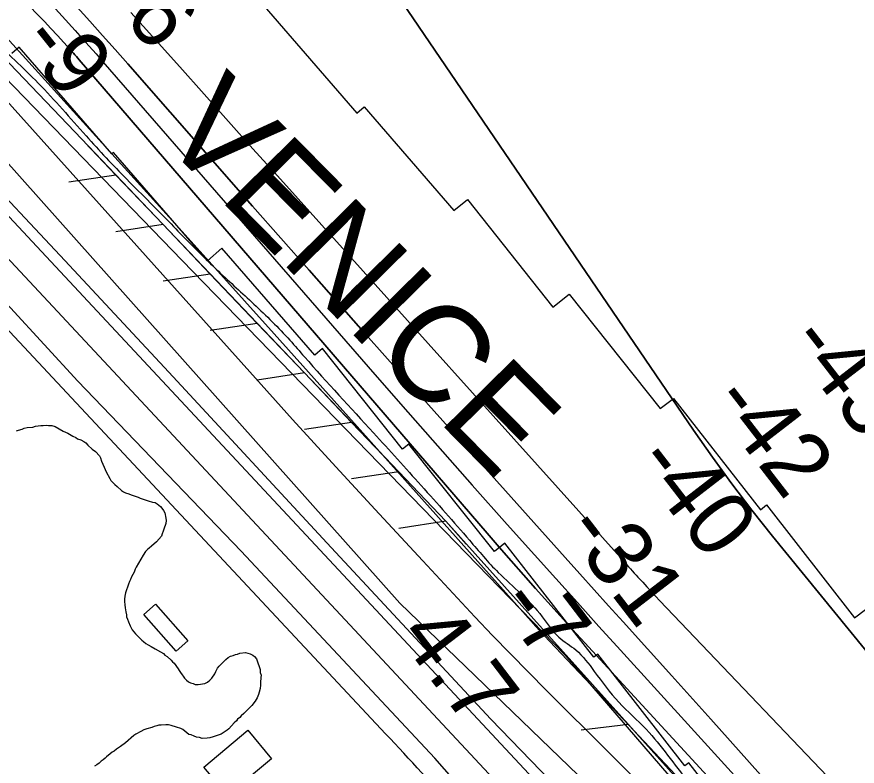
# Model space of a CAD drawing. Extents: x 3887375 to 3925618, y 296674 to 322633.
# Drawn here: x 3897472 to 3898333, y 306817 to 307585 of the extents above; entities that cross this region are included whole.
import ezdxf

# ---------------------------------------------------------------- set-up
doc = ezdxf.new("R2010")
doc.units = 0
for name, color, linetype in [('V-BLDG-OTLN', 7, 'Continuous'), ('V-LEVE-TOET', 7, 'Continuous'), ('V-RIVR-EDGE', 7, 'Continuous'), ('V-RIVR-RANG', 7, 'Continuous'), ('V-ROAD-CNTR', 7, 'Continuous'), ('V-RRAP-FSHR', 7, 'Continuous'), ('V-RRAP-RVMT', 7, 'Continuous'), ('V-RRAP-RVMT-IDEN', 7, 'Continuous'), ('V-SITE-VEGE', 7, 'Continuous'), ('V-SURV-LINE', 7, 'Continuous'), ('V-TOPO-DPTH', 7, 'Continuous'), ('V-TOPO-MINR', 7, 'Continuous'), ('V-TOPO-WATR', 7, 'Continuous')]:
    doc.layers.add(name, color=color, linetype=linetype)

msp = doc.modelspace()

# ---------------------------------------------------------------- linework, layer by layer
at = {"layer": 'V-BLDG-OTLN'}
for points in [[(3897614.19, 306982.77), (3897647.31, 306945.17), (3897635.62, 306934.86), (3897602.49, 306972.46)], [(3897663.96, 306816.07), (3897708.98, 306853.67), (3897733.3, 306824.55), (3897692.27, 306790.28), (3897684.88, 306799.12), (3897680.9, 306795.79)]]:
    msp.add_lwpolyline(points, close=True, dxfattribs=at)
at = {"layer": 'V-LEVE-TOET'}
for points in [[(3897628.06, 307220.48), (3897521.51, 307335.13), (3897424.58, 307438.31), (3897303.19, 307570.56), (3897169.65, 307712.92), (3897111.57, 307774.39), (3897068.91, 307820.25), (3896991.6, 307903.28), (3896953.77, 307940.82), (3896894.73, 307997.31), (3896828.08, 308063.5), (3896761.22, 308129.88), (3896689.75, 308201.41), (3896624.29, 308266.41), (3896558.04, 308331.41), (3896467.95, 308421.71), (3896374.06, 308516.16), (3896282.17, 308609.23), (3896193.87, 308699.73), (3896084.36, 308810.99), (3895985.85, 308912.76), (3895925.79, 308973.83)], [(3898424.48, 306234.02), (3898251.66, 306432.44), (3898086.45, 306611.84), (3898044.55, 306661.29), (3897900.68, 306825.16), (3897702.28, 307037.07), (3897534.9, 307211.24), (3897361.93, 307399.16)], [(3897628.06, 307220.48), (3897794.32, 307041.06), (3897958.05, 306864.95)], [(3897958.05, 306864.95), (3898152.73, 306664.02), (3898271.21, 306545.58), (3898354.85, 306454.31)]]:
    msp.add_lwpolyline(points, dxfattribs=at)
at = {"layer": 'V-RIVR-EDGE'}
msp.add_spline([(3894498.05, 310522.42), (3894530.03, 310496.11), (3894553.78, 310474.69), (3894579.94, 310451.31), (3894614.83, 310419.17), (3894633.24, 310400.67), (3894662.79, 310372.43), (3894685.08, 310353.44), (3894692.35, 310347.11), (3894709.79, 310328.13), (3894746.59, 310285.3), (3894785.84, 310252.18), (3894809.57, 310225.9), (3894830.41, 310205.45), (3894852.71, 310189.85), (3894866.75, 310171.85), (3894915.18, 310120.25), (3894950.06, 310083.74), (3894971.37, 310062.81), (3894999, 310039.43), (3895025.16, 310017.03), (3895052.79, 309992.68), (3895092.99, 309952.27), (3895110.91, 309932.8), (3895141.44, 309903.1), (3895188.91, 309855.88), (3895222.82, 309821.31), (3895255.75, 309784.32), (3895319.22, 309722.49), (3895350.7, 309688.42), (3895358.44, 309676.26), (3895364.73, 309669.44), (3895374.92, 309663.11), (3895388.97, 309650.44), (3895410.77, 309628.05), (3895448.54, 309583.28), (3895480.52, 309554.06), (3895503.76, 309527.78), (3895533.8, 309499.54), (3895577.4, 309454.75), (3895606.95, 309425.54), (3895653.45, 309378.81), (3895685.92, 309349.1), (3895719.83, 309314.54), (3895749.38, 309285.81), (3895790.55, 309242.49), (3895837.06, 309195.75), (3895863.69, 309164.12), (3895900.02, 309127.61), (3895944.1, 309081.37), (3895955.73, 309070.65), (3895974.63, 309054.58), (3896002.25, 309033.14), (3896032.78, 309003.93), (3896062.81, 308972.29), (3896082.67, 308950.39), (3896119.48, 308911.93), (3896139.34, 308892.46), (3896151.96, 308889.51), (3896163.12, 308883.66), (3896167.95, 308873.93), (3896170.35, 308862.27), (3896184.39, 308844.27), (3896211.03, 308816.04), (3896224.12, 308810.18), (3896236.73, 308802.37), (3896249.8, 308786.8), (3896255.61, 308776.59), (3896270.64, 308766.35), (3896280.32, 308753.22), (3896295.82, 308737.15), (3896375.27, 308661.2), (3896425.17, 308610.08), (3896464.41, 308570.65), (3896519.63, 308515.64), (3896548.69, 308483.03), (3896563.22, 308467.45), (3896597.61, 308430.94), (3896635.89, 308396.37), (3896666.41, 308365.7), (3896681.42, 308349.64), (3896712.43, 308320.42), (3896746.34, 308287.31), (3896777.36, 308260.04), (3896801.58, 308235.7), (3896820.47, 308215.26), (3896842.76, 308195.29), (3896851.46, 308181.19), (3896882.46, 308148.57), (3896918.81, 308116.43), (3896962.9, 308074.56), (3896997.76, 308033.19), (3897029.24, 307998.63), (3897042.32, 307985), (3897083.5, 307945.57), (3897107.23, 307918.31), (3897123.21, 307898.85), (3897130, 307898.83), (3897142.13, 307892.97), (3897145.99, 307882.28), (3897149.85, 307874.01), (3897162.93, 307860.38), (3897188.6, 307833.12), (3897229.29, 307788.83), (3897267.56, 307752.31), (3897300.5, 307715.81), (3897334.4, 307680.27), (3897361.53, 307651.07), (3897384.78, 307628.19), (3897411.42, 307598.98), (3897445.81, 307563.45), (3897494.26, 307516.71), (3897543.17, 307462.68), (3897584.83, 307418.38), (3897609.05, 307394.04), (3897646.83, 307355.58), (3897678.81, 307323.94), (3897715.15, 307290.34), (3897751.96, 307253.34), (3897766.97, 307236.31), (3897837.68, 307158.43), (3897886.6, 307104.4), (3897936, 307048.43), (3897965.54, 307015.34), (3898010.59, 306970.06), (3898027.54, 306949.14), (3898044.99, 306935.98), (3898063.87, 306914.08), (3898089.05, 306882.46), (3898117.14, 306854.7), (3898160.23, 306801.18), (3898195.59, 306763.7), (3898235.79, 306719.89), (3898261.46, 306693.6), (3898297.3, 306650.78), (3898332.65, 306612.33), (3898369.94, 306568.04), (3898397.54, 306534.95), (3898422.23, 306505.75), (3898462.9, 306455.14), (3898495.34, 306417.18), (3898521.97, 306382.15), (3898601.37, 306284.34), (3898652.22, 306228.37), (3898693.37, 306177.28), (3898729.68, 306130.57), (3898777.13, 306074.12), (3898825.55, 306014.26), (3898848.79, 305986.04), (3898903.98, 305917.43), (3898957.25, 305854.65), (3898984.35, 305818.16), (3899049.73, 305744.67), (3899107.84, 305679.45), (3899129.14, 305651.72), (3899142.69, 305630.31), (3899156.24, 305611.83), (3899175.12, 305587.98), (3899224.03, 305529.59), (3899255.99, 305493.57), (3899288.9, 305449.3), (3899312.61, 305415.24), (3899375.55, 305336.9), (3899410.9, 305296.02), (3899442.85, 305252.24), (3899470.43, 305211.86), (3899531.42, 305133.52), (3899579.35, 305071.24), (3899616.14, 305025.99), (3899647.13, 304986.09), (3899690.7, 304931.1), (3899729.41, 304876.62), (3899753.62, 304846.93), (3899770.56, 304821.64), (3899817.5, 304755.48), (3899845.56, 304713.16), (3899868.3, 304677.16), (3899889.6, 304650.4), (3899911.39, 304623.64), (3899955.44, 304569.14), (3899987.39, 304526.81), (3900012.56, 304494.21), (3900025.63, 304476.21), (3900037.24, 304456.75), (3900061.94, 304431.93), (3900070.67, 304424.13), (3900074.53, 304414.41), (3900074.99, 304404.21), (3900073.03, 304397.9), (3900071.55, 304388.68), (3900071.54, 304383.82), (3900075.9, 304378.96), (3900087.05, 304374.07), (3900096.26, 304367.74), (3900108.39, 304362.37), (3900117.11, 304353.6), (3900140.84, 304326.35), (3900165.54, 304299.09), (3900226.07, 304227.55), (3900277.87, 304164.29), (3900319.98, 304105.91), (3900352.41, 304062.61), (3900384.36, 304023.2), (3900411.47, 303988.16), (3900438.1, 303954.1), (3900462.8, 303926.85), (3900556.24, 303812.49), (3900597.89, 303762.85), (3900633.71, 303716.63), (3900652.59, 303691.33), (3900701.96, 303626.62), (3900774.57, 303530.77), (3900849.12, 303437.34), (3900903.35, 303371.16), (3900928.05, 303343.42), (3900948.87, 303317.63), (3901001.17, 303258.26), (3901038.95, 303216.88), (3901074.78, 303173.09), (3901092.2, 303147.31), (3901171.6, 303050.47), (3901205, 303008.62), (3901238.41, 302968.23), (3901274.74, 302927.83), (3901303.3, 302893.77), (3901343.98, 302847.53), (3901366.73, 302816.4), (3901404.5, 302770.17), (3901454.38, 302715.17), (3901507.18, 302659.19), (3901551.73, 302608.09), (3901584.66, 302570.61), (3901650.02, 302491.29), (3901680.99, 302443.62), (3901717.76, 302388.17), (3901785.52, 302298.16), (3901789.55, 302293.3)], degree=3, dxfattribs=at)
at = {"layer": 'V-ROAD-CNTR'}
msp.add_lwpolyline([(3897850.15, 306850.22), (3897084.5, 307668.93)], dxfattribs=at)
msp.add_spline([(3898676.43, 305915.91), (3898551.87, 306070.29), (3898364.89, 306290.32), (3898192.19, 306484.1), (3897998.73, 306690.52), (3897850.15, 306850.22)], degree=3, dxfattribs=at)
at = {"layer": 'V-RRAP-FSHR'}
for p, q in [((3897573.77, 307422.51), (3897525.49, 307415.18)), ((3897622.06, 307371.84), (3897573.78, 307364.52)), ((3897670.36, 307321.17), (3897622.08, 307313.85)), ((3897718.66, 307270.5), (3897670.38, 307263.18)), ((3897766.95, 307219.84), (3897718.67, 307212.51)), ((3897815.25, 307169.17), (3897766.97, 307161.84)), ((3897863.55, 307118.5), (3897815.27, 307111.17)), ((3897911.84, 307067.83), (3897863.57, 307060.51)), ((3898098.95, 306859.53), (3898050.48, 306853.64))]:
    msp.add_line(p, q, dxfattribs=at)
for points in [[(3891468.38, 312810.08), (3891592.07, 312735.45), (3892299.93, 312230.23), (3893039.21, 311719.28), (3893631.65, 311277.12), (3894117.75, 310846), (3894636.93, 310371.58), (3895241.96, 309786.83), (3895348.82, 309658.26), (3895604.32, 309398.25), (3896430.18, 308555.06), (3897023.94, 307973.73), (3897641.56, 307335.08), (3898033.61, 306930.91), (3898562.18, 306317.87), (3899280.35, 305434.23), (3899629.7, 304981.52), (3900046.19, 304414.8), (3900422.65, 303959.37), (3901188.76, 303011.8), (3901775.81, 302279.78)], [(3900183.19, 304271.3), (3899817.13, 304740.59), (3899520.95, 305137.04), (3899332.27, 305381.1), (3899099.29, 305675.47), (3898876.14, 305945.24), (3898644, 306227.35), (3898359.55, 306569.44), (3897911.75, 307067.92), (3897531.56, 307466.79), (3897152.78, 307863.36), (3896930.63, 308096.06), (3896288.11, 308742.08), (3895667.71, 309363.71), (3895267.02, 309773.18), (3894693.57, 310343.47)], [(3897573.77, 307422.51), (3897541.9, 307455.94)], [(3897622.06, 307371.84), (3897573.77, 307422.51)], [(3897670.36, 307321.17), (3897622.06, 307371.84)], [(3897718.66, 307270.5), (3897670.36, 307321.17)], [(3897766.95, 307219.84), (3897718.66, 307270.51)], [(3897815.25, 307169.17), (3897766.95, 307219.84)], [(3897863.55, 307118.5), (3897815.25, 307169.17)], [(3897911.84, 307067.83), (3897911.75, 307067.92), (3897863.55, 307118.5)], [(3897932.79, 307044.51), (3897911.84, 307067.83)], [(3898098.95, 306859.53), (3898077.57, 306883.34)], [(3898145.73, 306807.46), (3898098.95, 306859.54)]]:
    msp.add_lwpolyline(points, dxfattribs=at)
at = {"layer": 'V-RRAP-RVMT'}
for p, q in [((3897725.62, 307595.67), (3897820.77, 307486)), ((3897474.5, 307553.64), (3897467.16, 307547.28)), ((3897569.54, 307444.17), (3897474.5, 307553.64)), ((3897820.77, 307486), (3897828.19, 307492.35)), ((3897828.19, 307492.35), (3897920.15, 307386.41)), ((3897571.34, 307445.73), (3897569.54, 307444.17)), ((3897667.77, 307334.74), (3897571.34, 307445.73)), ((3897920.15, 307386.41), (3897934.1, 307397.41)), ((3897934.1, 307397.41), (3898021.6, 307287.3)), ((3897682.39, 307347.52), (3897667.77, 307334.74)), ((3897777.5, 307238.08), (3897682.39, 307347.52)), ((3898021.6, 307287.3), (3898038.25, 307300.49)), ((3898038.25, 307300.49), (3898131.4, 307183.22)), ((3897785.49, 307245.02), (3897777.5, 307238.08)), ((3897867.56, 307141.69), (3897785.49, 307245.02)), ((3898131.4, 307183.22), (3898144.94, 307193.78)), ((3898144.94, 307193.78), (3898234.04, 307079.59)), ((3897874.07, 307146.88), (3897867.56, 307141.69)), ((3897961.58, 307036.81), (3897874.07, 307146.88)), ((3898234.04, 307079.59), (3898240.41, 307084.56)), ((3898240.41, 307084.56), (3898330.66, 306968.92)), ((3897972.31, 307045.36), (3897961.58, 307036.81)), ((3898063.43, 306928.57), (3897972.31, 307045.36)), ((3898330.66, 306968.92), (3898341.67, 306977.5)), ((3898067.4, 306931.66), (3898063.43, 306928.57)), ((3898156.73, 306817.18), (3898067.4, 306931.66)), ((3898160.84, 306820.38), (3898156.73, 306817.18)), ((3898251.12, 306704.69), (3898160.84, 306820.38))]:
    msp.add_line(p, q, dxfattribs=at)
at = {"layer": 'V-SITE-VEGE'}
for points in [[(3897472.04, 307160.44), (3897474.15, 307161.2), (3897477.57, 307162.2), (3897479.94, 307163.22), (3897482.83, 307163.96), (3897488.6, 307164.41), (3897491.48, 307165.15), (3897496.73, 307165.86), (3897499.09, 307166.09), (3897502.5, 307166.31), (3897504.85, 307166.01), (3897507.99, 307165.97), (3897511.38, 307164.88), (3897519.69, 307160.05), (3897522.03, 307158.97), (3897524.38, 307158.15), (3897529.58, 307155.2), (3897532.7, 307153.59), (3897534.51, 307152.26), (3897537.9, 307151.16), (3897540.76, 307149.55), (3897542.83, 307148.21), (3897545.16, 307145.83), (3897549.55, 307141.84)], [(3897549.55, 307141.84), (3897552.92, 307139.17), (3897557.05, 307134.93), (3897558.07, 307132.82), (3897559.07, 307129.4), (3897561.87, 307123.34)], [(3897561.87, 307123.34), (3897563.89, 307118.34), (3897567.47, 307111.74), (3897568.75, 307109.63), (3897570.55, 307107.51), (3897572.62, 307105.39), (3897574.95, 307103.52), (3897579.35, 307099.53), (3897581.68, 307097.93), (3897583.76, 307096.85), (3897586.89, 307096.03), (3897589.5, 307094.95), (3897593.67, 307093.58), (3897596.53, 307092.49), (3897598.61, 307091.42), (3897606.96, 307088.95), (3897611.38, 307087.31), (3897614.12, 307087.21), (3897615.93, 307085.61), (3897617.75, 307084.28), (3897619.3, 307082.95), (3897620.85, 307081.36), (3897622.65, 307078.98), (3897623.93, 307076.34), (3897624.9, 307071.09), (3897625.13, 307068.73), (3897624.82, 307065.59), (3897622.91, 307059.86), (3897622.36, 307057.77), (3897621.01, 307054.91), (3897620.46, 307052.56), (3897615.4, 307046.87), (3897610.11, 307042.49), (3897607.98, 307040.42), (3897606.39, 307039.14), (3897604.27, 307036.81), (3897601.86, 307033.18), (3897594.62, 307020.97), (3897593.55, 307018.89), (3897592.46, 307015.76), (3897589.77, 307010.83), (3897588.69, 307008.22), (3897587.61, 307006.14), (3897586.79, 307003.27), (3897583.52, 306994.41), (3897582.95, 306991.02), (3897582.65, 306988.14), (3897582.62, 306985.79), (3897582.83, 306982.12), (3897583.31, 306979.23), (3897583.78, 306975.03), (3897584.52, 306971.88), (3897584.76, 306969.78), (3897585.51, 306967.42), (3897586.52, 306964.79), (3897588.3, 306960.83), (3897590.6, 306956.61), (3897593.69, 306952.64), (3897598.59, 306947.6), (3897600.4, 306946), (3897602.22, 306944.67), (3897604.54, 306942.54), (3897606.88, 306941.2), (3897610, 306939.59), (3897614.16, 306937.17), (3897619.35, 306933.96), (3897622.47, 306932.35), (3897624.02, 306930.76), (3897626.35, 306929.15), (3897630.49, 306925.43), (3897631.78, 306923.84), (3897633.33, 306922.51), (3897637.44, 306916.69), (3897638.73, 306915.1), (3897640.01, 306912.73), (3897641.55, 306910.61), (3897642.84, 306909.03), (3897644.12, 306907.17), (3897646.19, 306905.05), (3897648, 306903.45), (3897650.34, 306902.38), (3897652.95, 306901.56), (3897655.03, 306900.74), (3897658.17, 306900.7), (3897664.73, 306901.65), (3897667.63, 306902.92), (3897670.02, 306904.99), (3897672.14, 306907.05), (3897675.08, 306911.46), (3897676.16, 306914.07), (3897677.77, 306917.18), (3897679.64, 306919.26), (3897680.96, 306920.81), (3897686.54, 306926.23), (3897688.92, 306928.29), (3897691.3, 306929.57), (3897693.93, 306930.32), (3897696.3, 306931.33), (3897698.4, 306931.83), (3897700.77, 306932.58), (3897706.54, 306933.29)], [(3897706.54, 306933.29), (3897711.5, 306932.17), (3897714.09, 306930.57), (3897715.91, 306929.23), (3897717.71, 306926.85), (3897718.98, 306923.95), (3897720.99, 306918.16), (3897721.49, 306916.06), (3897721.71, 306912.92), (3897722.45, 306910.03), (3897722.42, 306907.93), (3897721.83, 306902.71), (3897721.79, 306899.82), (3897721.48, 306896.43), (3897720.64, 306892.77), (3897719.83, 306890.42), (3897718.47, 306887.04), (3897716.33, 306883.4), (3897713.12, 306878.99), (3897704.9, 306870.99), (3897701.98, 306868.41), (3897700.65, 306866.86), (3897698.53, 306865.06), (3897697.2, 306863.5), (3897695.08, 306861.44), (3897689.49, 306855.23), (3897687.64, 306853.68), (3897681.56, 306849.84), (3897678.4, 306848.57), (3897675.51, 306847.57), (3897673.41, 306847.07), (3897669.99, 306846.07), (3897667.37, 306845.58), (3897662.12, 306845.13), (3897659.26, 306846.22), (3897656.39, 306846.78), (3897654.04, 306847.6), (3897650.92, 306848.95), (3897648.57, 306849.51), (3897642.35, 306854.57), (3897640.27, 306855.64), (3897635.83, 306856.75), (3897630.36, 306858.66), (3897627.75, 306859.22), (3897624.87, 306859.26), (3897620.15, 306858.8), (3897617.8, 306858.83), (3897615.69, 306858.08), (3897612.81, 306857.59), (3897610.43, 306856.58), (3897605.44, 306855.08), (3897602.54, 306854.07), (3897599.38, 306852.54), (3897594.11, 306849.73), (3897591.99, 306848.19), (3897583.51, 306840.97), (3897578.48, 306837.12), (3897574.26, 306834.29), (3897571.87, 306832.23), (3897570.02, 306831.21), (3897567.91, 306829.67), (3897564.2, 306826.58), (3897562.61, 306825.03), (3897560.75, 306823.48), (3897558.64, 306821.94), (3897556.52, 306820.14), (3897554.14, 306818.34), (3897551.76, 306816.8)]]:
    msp.add_lwpolyline(points, dxfattribs=at)
at = {"layer": 'V-SURV-LINE'}
for points in [[(3897031.45, 307843.79), (3898172.82, 306620.58)], [(3898150.87, 306600.12), (3897009.5, 307823.33)]]:
    msp.add_lwpolyline(points, dxfattribs=at)
at = {"layer": 'V-TOPO-DPTH'}
for points in [[(3898438.22, 306817.84), (3898246.53, 307052.71), (3898225.47, 307079.2), (3898204.88, 307106.05), (3898185, 307133.42), (3898165.58, 307161.14), (3897872.75, 307591.01), (3897856.09, 307615.25), (3897839.31, 307639.39), (3897822.32, 307663.39), (3897805.19, 307687.3), (3897776.06, 307727.62), (3897773.38, 307731.28), (3897770.66, 307734.9), (3897767.89, 307738.49), (3897765.08, 307742.05), (3897720.03, 307798.29), (3897694.43, 307829.74), (3897668.5, 307860.92), (3897642.08, 307891.68), (3897615.33, 307922.16), (3897305.24, 308269.96)], [(3898438.22, 306817.84), (3898246.53, 307052.71), (3898225.47, 307079.2), (3898204.88, 307106.05), (3898185, 307133.42), (3898165.58, 307161.14), (3897872.75, 307591.01), (3897856.09, 307615.25), (3897839.31, 307639.39), (3897822.32, 307663.39), (3897805.19, 307687.3), (3897776.06, 307727.62), (3897773.38, 307731.28), (3897770.66, 307734.9), (3897767.89, 307738.49), (3897765.08, 307742.05), (3897720.03, 307798.29), (3897694.43, 307829.74), (3897668.5, 307860.92), (3897642.08, 307891.68), (3897615.33, 307922.16), (3897305.24, 308269.96)], [(3897116.59, 307883.36), (3897710.89, 307220.91), (3897754.84, 307172.22), (3897798.99, 307123.72), (3897843.44, 307075.48), (3897888.08, 307027.42), (3897941.66, 306970.1), (3897959.76, 306950.95), (3897978.01, 306931.92), (3897996.46, 306913.1), (3898015.05, 306894.41), (3898272.83, 306638.13)], [(3897448.11, 307689.53), (3897534.06, 307594.62), (3897547.11, 307580.16), (3897560.11, 307565.65), (3897573.04, 307551.08), (3897585.93, 307536.47), (3897713.85, 307390.81), (3897771.83, 307325), (3897829.93, 307259.29), (3897888.23, 307193.75), (3897946.65, 307128.33), (3898034.18, 307030.62), (3898048.95, 307014.15), (3898063.73, 306997.69), (3898078.54, 306981.25), (3898093.35, 306964.82), (3898143.43, 306909.36), (3898183.22, 306865.14), (3898222.9, 306820.83), (3898262.43, 306776.38)], [(3898262.43, 306776.38), (3898222.9, 306820.83), (3898183.22, 306865.14), (3898143.43, 306909.36), (3898093.35, 306964.82), (3898078.54, 306981.25), (3898063.73, 306997.69), (3898048.95, 307014.15), (3898034.18, 307030.62), (3897946.65, 307128.33), (3897888.23, 307193.75), (3897829.93, 307259.29), (3897771.83, 307325), (3897713.85, 307390.81), (3897585.93, 307536.47), (3897573.04, 307551.08), (3897560.11, 307565.65), (3897547.11, 307580.16), (3897534.06, 307594.62), (3897448.11, 307689.53)], [(3898234.67, 306747.1), (3898054.35, 306943.22), (3898041.65, 306957.1), (3898028.98, 306971.01), (3898016.38, 306984.98), (3898003.82, 306998.98), (3897991.32, 307013.04), (3897978.88, 307027.15), (3897966.51, 307041.33), (3897954.2, 307055.55), (3897536.26, 307540.75), (3897533.32, 307544.12), (3897531.83, 307545.8), (3897530.34, 307547.46), (3897520.33, 307558.54), (3897513.8, 307565.7), (3897507.22, 307572.82), (3897500.56, 307579.88), (3897493.87, 307586.89), (3897414.7, 307668.98)], [(3898234.67, 306747.1), (3898054.35, 306943.22), (3898041.65, 306957.1), (3898028.98, 306971.01), (3898016.38, 306984.98), (3898003.82, 306998.98), (3897991.32, 307013.04), (3897978.88, 307027.15), (3897966.51, 307041.33), (3897954.2, 307055.55), (3897536.26, 307540.75), (3897533.32, 307544.12), (3897531.83, 307545.8), (3897530.34, 307547.46), (3897520.33, 307558.54), (3897513.8, 307565.7), (3897507.22, 307572.82), (3897500.56, 307579.88), (3897493.87, 307586.89), (3897414.7, 307668.98)], [(3897589.23, 307589.06), (3897614.24, 307561.18), (3897639.23, 307533.28), (3897664.2, 307505.38), (3897689.19, 307477.48), (3897714.2, 307449.6), (3897739.22, 307421.73), (3898093.33, 307027.6), (3898095.24, 307025.47), (3898097.15, 307023.35), (3898099.05, 307021.22), (3898100.96, 307019.09), (3898102.87, 307016.96), (3898104.78, 307014.84), (3898106.7, 307012.72), (3898108.63, 307010.61), (3898113.5, 307005.29), (3898117.88, 307000.53), (3898122.27, 306995.79), (3898126.7, 306991.08), (3898131.15, 306986.39), (3898338.38, 306769.17)], [(3897589.23, 307589.06), (3897614.24, 307561.18), (3897639.23, 307533.28), (3897664.2, 307505.38), (3897689.19, 307477.48), (3897714.2, 307449.6), (3897739.22, 307421.73), (3898093.33, 307027.6), (3898095.24, 307025.47), (3898097.15, 307023.35), (3898099.05, 307021.22), (3898100.96, 307019.09), (3898102.87, 307016.96), (3898104.78, 307014.84), (3898106.7, 307012.72), (3898108.63, 307010.61), (3898113.5, 307005.29), (3898117.88, 307000.53), (3898122.27, 306995.79), (3898126.7, 306991.08), (3898131.15, 306986.39), (3898338.38, 306769.17)]]:
    msp.add_lwpolyline(points, dxfattribs=at)
at = {"layer": 'V-TOPO-MINR'}
for points in [[(3897305.24, 308269.96), (3897615.33, 307922.16), (3897642.08, 307891.68), (3897668.5, 307860.92), (3897694.43, 307829.74), (3897720.03, 307798.29), (3897765.08, 307742.05), (3897767.89, 307738.49), (3897770.66, 307734.9), (3897773.38, 307731.28), (3897776.06, 307727.62), (3897805.19, 307687.3), (3897822.32, 307663.39), (3897839.31, 307639.39), (3897856.09, 307615.25), (3897872.75, 307591.01), (3898165.58, 307161.14), (3898185, 307133.42), (3898204.88, 307106.05), (3898225.47, 307079.2), (3898246.53, 307052.71), (3898438.22, 306817.84)], [(3896792.57, 308187.58), (3897864.78, 306984.03)], [(3897448.11, 307689.53), (3897534.06, 307594.62), (3897547.11, 307580.16), (3897560.11, 307565.65), (3897573.04, 307551.08), (3897585.93, 307536.47), (3897713.85, 307390.81), (3897771.83, 307325), (3897829.93, 307259.29), (3897888.23, 307193.75), (3897946.65, 307128.33), (3898034.18, 307030.62), (3898048.95, 307014.15), (3898063.73, 306997.69), (3898078.54, 306981.25), (3898093.35, 306964.82), (3898143.43, 306909.36), (3898183.22, 306865.14), (3898222.9, 306820.83), (3898262.43, 306776.38)], [(3897414.7, 307668.98), (3897493.87, 307586.89), (3897500.56, 307579.88), (3897507.22, 307572.82), (3897513.8, 307565.7), (3897520.33, 307558.54), (3897530.34, 307547.46), (3897531.83, 307545.8), (3897533.32, 307544.12), (3897536.26, 307540.75), (3897954.2, 307055.55), (3897966.51, 307041.33), (3897978.88, 307027.15), (3897991.32, 307013.04), (3898003.82, 306998.98), (3898016.38, 306984.98), (3898028.98, 306971.01), (3898041.65, 306957.1), (3898054.35, 306943.22), (3898234.67, 306747.1)], [(3897454.28, 307656.2), (3897485.11, 307622.45), (3897532.16, 307570.51), (3897539.29, 307562.58), (3897546.39, 307554.63), (3897553.45, 307546.63), (3897560.47, 307538.61), (3897832.35, 307226.08), (3897867.75, 307185.55), (3897903.27, 307145.12), (3897938.95, 307104.84), (3897974.74, 307064.66), (3898002.52, 307033.6), (3898024.54, 307009.05), (3898046.6, 306984.54), (3898068.73, 306960.1), (3898090.9, 306935.69), (3898163.17, 306856.36), (3898221.37, 306792.2)], [(3897589.23, 307589.06), (3897614.24, 307561.18), (3897639.23, 307533.28), (3897664.2, 307505.38), (3897689.19, 307477.48), (3897714.2, 307449.6), (3897739.22, 307421.73), (3898093.33, 307027.6), (3898095.24, 307025.47), (3898097.15, 307023.35), (3898099.05, 307021.22), (3898100.96, 307019.09), (3898102.87, 307016.96), (3898104.78, 307014.84), (3898106.7, 307012.72), (3898108.63, 307010.61), (3898113.5, 307005.29), (3898117.88, 307000.53), (3898122.27, 306995.79), (3898126.7, 306991.08), (3898131.15, 306986.39), (3898338.38, 306769.17)], [(3897461.72, 307563.41), (3897553.33, 307462.48), (3897644.74, 307361.38), (3897735.87, 307260.03), (3897826.82, 307158.51), (3897999.13, 306965.61), (3898003.8, 306960.43), (3898008.49, 306955.27), (3898013.23, 306950.16), (3898017.99, 306945.07), (3898072.52, 306887.32), (3898104.55, 306853.35), (3898136.56, 306819.36), (3898168.52, 306785.33)], [(3897864.78, 306984.03), (3898490.34, 306380.34), (3898912.29, 305880.81), (3899084.36, 305640.02), (3899155.82, 305557.68), (3899225.57, 305473.89), (3899294.18, 305389.12), (3899378.54, 305282.66), (3899404.15, 305250.43), (3899429.81, 305218.23), (3899455.54, 305186.1), (3899481.32, 305154), (3899540.75, 305080.19)]]:
    msp.add_lwpolyline(points, dxfattribs=at)
at = {"layer": 'V-TOPO-WATR'}
msp.add_lwpolyline([(3897116.59, 307883.36), (3897710.89, 307220.91), (3897754.84, 307172.22), (3897798.99, 307123.72), (3897843.44, 307075.48), (3897888.08, 307027.42), (3897941.66, 306970.1), (3897959.76, 306950.95), (3897978.01, 306931.92), (3897996.46, 306913.1), (3898015.05, 306894.41), (3898272.83, 306638.13)], dxfattribs=at)

# ---------------------------------------------------------------- texts
at = {"layer": 'V-RIVR-RANG'}
for s, rotation, p in [('-36', 308.93267, (3897530.18, 307646.76)), ('-9', 308.64833, (3897473.05, 307558.74)), ('-43', 307.66331, (3898260.4, 307251.38)), ('-42', 307.66331, (3898181.42, 307190.06)), ('-40', 307.66331, (3898103.23, 307127.69)), ('-31', 307.66331, (3898030.69, 307058.01)), ('-7', 307.37833, (3897962.91, 306982.56)), ('4.7', 307.37833, (3897861.66, 306950.37))]:
    msp.add_text(s, height=67, rotation=rotation, dxfattribs=at).set_placement(p)
at = {"layer": 'V-RRAP-RVMT-IDEN'}
msp.add_text('VENICE', height=100, rotation=314.58447, dxfattribs=at).set_placement((3897615.5, 307462.9))

doc.saveas('drawing.dxf')
